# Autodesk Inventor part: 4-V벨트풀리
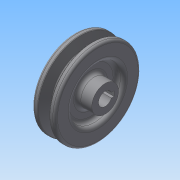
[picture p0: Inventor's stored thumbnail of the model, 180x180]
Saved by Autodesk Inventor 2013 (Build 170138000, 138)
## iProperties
Created: 2015-02
Part Number: 4-V벨트풀리
Material: 일반
Document SubType Name: Modeling
Designer: Administrator
Density: 1 g/cm^3
Author: Administrator
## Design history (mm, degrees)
sketch "스케치1"
  geometry: L1 (0, 0)-(-25, 0); L2 (-25, 5.5)-(0, 5.5); L3 (0, 5.5)-(0, 11); L4 (0, 11)-(-12, 11); L5 (-12, 11)-(-12, 21.5); L6 (-12, 21.5)-(-6, 21.5); L7 (-6, 21.5)-(-6, 35.2); L8 (-6, 35.2)-(-10.675, 35.2); L9 (-10.675, 35.2)-(-13.426, 26.2); L10 (-13.426, 26.2)-(-17.574, 26.2); L11 (-17.574, 26.2)-(-20.325, 35.2); L12 (-20.325, 35.2)-(-25, 35.2); L13 (-25, 35.2)-(-25, 21.5); L14 (-25, 21.5)-(-19, 21.5); L15 (-19, 21.5)-(-19, 11); L16 (-19, 11)-(-25, 11); L17 (-25, 11)-(-25, 5.5); 2 further points
  constraints: 34 end point, 13 parallel, 3 equal length, 3 vertical alignment, 2 collinear, 2 horizontal alignment, 2 point on line, 1 horizontal, 1 perpendicular
  dimensions: "d0" = 25 distance of L1.start L1.end; "d1" = 6 distance of L13.end L14.end; "d2" = 11 diameter of L2 L1; "d3" = 22 diameter of L4 L1; "d4" = 43 diameter of L14 L1; "d5" = 8 distance of point (-11.5, 32.5) point (-19.5, 32.5); "d6" = 34 deg angle of L9 L11; "d7" = 19 distance between parallel lines of L7 L13; "d8" = 2.7 distance from line of L12 point (-19.5, 32.5); "d9" = 6.3 distance from line of point (-19.5, 32.5) L10; "d10" = 65 diameter of point (-19.5, 32.5) L1
revolve "회전1" sketch "스케치1" stored, may be unused: angle "d11" = 90 deg
sketch "스케치2"
  geometry: L1 (-2, 5.123)-(-2, 7.3); L2 (-2, 7.3)-(2, 7.3); L3 (2, 7.3)-(2, 5.123); C1 r 11 at (0, 0) reference; A1 r 5.5 centre (0, 0) between (-2, 5.123) and (2, 5.123) reference; 1 further point
  constraints: 6 end point, 2 point on circle, 1 midpoint, 1 parallel, 1 perpendicular, 1 vertical, 1 vertical alignment
  dimensions: "d12" = 4 distance of L1.end L2.end; "d14" = 12.8 dimension on A1 L2
extrude "돌출1" cut sketch "스케치2" stored distance "d15" = 10; taper "d16" = 0 deg
fillet "모깎기1" dims "d17" = 2, "d18" = 1, "d19" = 0.5
fillet "모깎기2" dims "d20" = 3
node "솔리드1"
